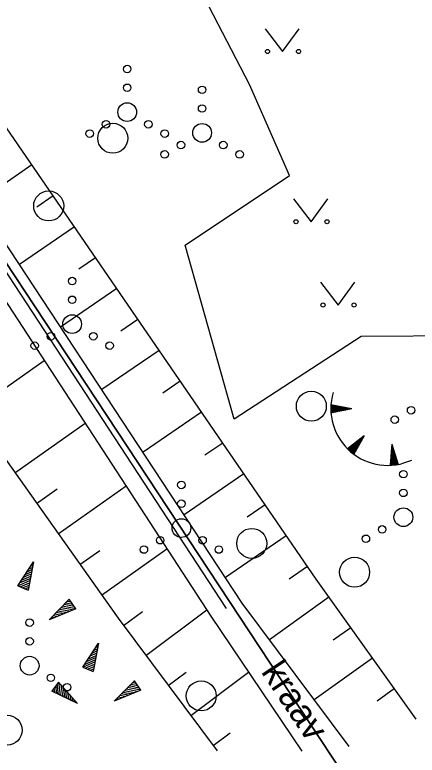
# Model space of a CAD drawing. Extents: x 554947 to 555436, y 6564938 to 6565792.
# Drawn here: x 555256.53 to 555267.27, y 6565099.76 to 6565119.52 of the extents above; entities that cross this region are included whole.
import ezdxf

# ---------------------------------------------------------------- set-up
doc = ezdxf.new("R2010")
doc.units = 0
for name, color, linetype in [('HALJASTUS', 7, 'Continuous'), ('PIIR', 7, 'Continuous'), ('RELJEEF', 7, 'Continuous'), ('VEEKOGU', 7, 'Continuous')]:
    doc.layers.add(name, color=color, linetype=linetype)

msp = doc.modelspace()

# ---------------------------------------------------------------- linework, layer by layer
at = {"layer": 'HALJASTUS'}
for p, q in [((555263.213, 6565119.152), (555263.676, 6565118.545)), ((555263.676, 6565118.545), (555264.122, 6565119.152)), ((555263.973, 6565114.606), (555264.437, 6565113.999)), ((555264.437, 6565113.999), (555264.882, 6565114.606)), ((555264.693, 6565112.382), (555265.157, 6565111.775)), ((555265.157, 6565111.775), (555265.602, 6565112.382))]:
    msp.add_line(p, q, dxfattribs=at)
msp.add_lwpolyline([(555277.06, 6565106.584), (555277.255, 6565111.788), (555268.557, 6565110.949), (555265.778, 6565110.936), (555262.384, 6565108.727), (555261.075, 6565113.375), (555263.858, 6565115.236), (555262.795, 6565117.659), (555261.001, 6565121.133), (555260.129, 6565122.751), (555257.76, 6565125.864), (555253.762, 6565133.295), (555248.914, 6565136.251)], dxfattribs=at)
for centre, radius in [((555263.275, 6565118.545), 0.055), ((555264.104, 6565118.545), 0.055), ((555259.533, 6565118.076), 0.1), ((555259.533, 6565117.576), 0.1), ((555261.531, 6565117.522), 0.1), ((555259.533, 6565116.926), 0.25), ((555261.531, 6565117.022), 0.1), ((555258.968, 6565116.601), 0.1), ((555260.098, 6565116.601), 0.1), ((555259.148, 6565116.228), 0.4), ((555261.531, 6565116.372), 0.25), ((555258.533, 6565116.351), 0.1), ((555260.533, 6565116.351), 0.1), ((555260.966, 6565116.047), 0.1), ((555262.096, 6565116.047), 0.1), ((555260.531, 6565115.797), 0.1), ((555262.531, 6565115.797), 0.1), ((555257.438, 6565114.421), 0.4), ((555264.036, 6565113.999), 0.055), ((555264.864, 6565113.999), 0.055), ((555258.064, 6565112.415), 0.1), ((555258.064, 6565111.915), 0.1), ((555264.756, 6565111.775), 0.055), ((555265.585, 6565111.775), 0.055), ((555258.064, 6565111.265), 0.25), ((555257.499, 6565110.94), 0.1), ((555258.629, 6565110.94), 0.1), ((555257.064, 6565110.69), 0.1), ((555259.064, 6565110.69), 0.1), ((555264.445, 6565109.073), 0.4), ((555267.106, 6565108.964), 0.1), ((555266.671, 6565108.714), 0.1), ((555266.9, 6565107.259), 0.1), ((555260.978, 6565106.97), 0.1), ((555266.9, 6565106.759), 0.1), ((555260.978, 6565106.47), 0.1), ((555266.9, 6565106.109), 0.25), ((555260.978, 6565105.82), 0.25), ((555262.855, 6565105.411), 0.4), ((555266.335, 6565105.784), 0.1), ((555265.9, 6565105.534), 0.1), ((555260.413, 6565105.495), 0.1), ((555261.543, 6565105.495), 0.1), ((555259.978, 6565105.245), 0.1), ((555261.978, 6565105.245), 0.1), ((555265.6, 6565104.64), 0.4), ((555256.93, 6565103.295), 0.1), ((555256.93, 6565102.795), 0.1), ((555256.93, 6565102.145), 0.25), ((555257.495, 6565101.82), 0.1), ((555257.93, 6565101.57), 0.1), ((555261.507, 6565101.339), 0.4), ((555256.331, 6565100.424), 0.4)]:
    msp.add_circle(centre, radius, dxfattribs=at)
at = {"layer": 'PIIR'}
for points in [[(555293.54, 6565286.23), (555256.63, 6565245.54), (555254.61, 6565228.5), (555255.75, 6565226.79), (555261.42, 6565218.27), (555289.11, 6565186.6), (555315.28, 6565149.09), (555315.73, 6565134.86), (555310.07, 6565124.47), (555303.59, 6565115.89), (555291.54, 6565100.48), (555288.85, 6565092.31), (555275.41, 6565088.83), (555273.15, 6565087.34), (555239.11, 6565139), (555231.12, 6565150.64), (555225.89, 6565157.13), (555173.21, 6565166.35), (555173.84, 6565168.77), (555191.64, 6565237.48), (555195.28, 6565271.63)], [(555272.013, 6565013.369), (555140.74, 6565041.04), (555172.58, 6565163.93), (555173.21, 6565166.35), (555225.89, 6565157.13), (555231.12, 6565150.64), (555239.11, 6565139), (555273.15, 6565087.34), (555275.41, 6565088.83), (555288.85, 6565092.31), (555289.83, 6565088.53), (555290.166, 6565088.221)]]:
    msp.add_lwpolyline(points, dxfattribs=at)
at = {"layer": 'RELJEEF'}
for p, q in [((555256.993, 6565115.514), (555255.559, 6565114.531)), ((555257.558, 6565114.689), (555257.123, 6565114.391)), ((555258.123, 6565113.864), (555256.658, 6565112.86)), ((555258.688, 6565113.039), (555258.244, 6565112.734)), ((555259.254, 6565112.214), (555257.757, 6565111.188)), ((555259.819, 6565111.389), (555259.365, 6565111.078)), ((555260.384, 6565110.564), (555258.856, 6565109.517)), ((555255.383, 6565108.927), (555257.316, 6565110.297)), ((555260.95, 6565109.739), (555260.486, 6565109.422)), ((555264.966, 6565109.046), (555265.033, 6565109.1)), ((555264.966, 6565109.014), (555265.065, 6565109.093)), ((555264.966, 6565108.982), (555265.097, 6565109.087)), ((555264.967, 6565109.079), (555265.001, 6565109.106)), ((555264.967, 6565108.951), (555265.129, 6565109.081)), ((555264.968, 6565108.92), (555265.162, 6565109.075)), ((555265.526, 6565109.004), (555264.969, 6565109.112)), ((555265.526, 6565109.004), (555264.97, 6565108.895)), ((555264.98, 6565108.897), (555265.194, 6565109.069)), ((555265.033, 6565108.908), (555265.226, 6565109.062)), ((555265.086, 6565108.918), (555265.258, 6565109.056)), ((555265.139, 6565108.929), (555265.291, 6565109.05)), ((555265.192, 6565108.939), (555265.323, 6565109.044)), ((555265.245, 6565108.949), (555265.355, 6565109.037)), ((555265.298, 6565108.96), (555265.387, 6565109.031)), ((555265.351, 6565108.97), (555265.42, 6565109.025)), ((555265.404, 6565108.981), (555265.452, 6565109.019)), ((555265.457, 6565108.991), (555265.484, 6565109.013)), ((555261.515, 6565108.915), (555259.955, 6565107.845)), ((555256.539, 6565107.295), (555258.409, 6565108.62)), ((555265.858, 6565108.284), (555265.413, 6565107.932)), ((555265.858, 6565108.284), (555265.578, 6565107.791)), ((555265.716, 6565108.035), (555265.721, 6565108.176)), ((555265.743, 6565108.082), (555265.747, 6565108.197)), ((555265.77, 6565108.129), (555265.773, 6565108.217)), ((555265.796, 6565108.176), (555265.799, 6565108.237)), ((555265.823, 6565108.223), (555265.824, 6565108.258)), ((555262.08, 6565108.09), (555261.608, 6565107.766)), ((555265.461, 6565107.887), (555265.464, 6565107.973)), ((555265.485, 6565107.866), (555265.49, 6565107.993)), ((555265.51, 6565107.845), (555265.516, 6565108.013)), ((555265.534, 6565107.825), (555265.541, 6565108.034)), ((555265.558, 6565107.806), (555265.567, 6565108.054)), ((555265.583, 6565107.801), (555265.593, 6565108.074)), ((555265.61, 6565107.848), (555265.619, 6565108.095)), ((555265.636, 6565107.895), (555265.644, 6565108.115)), ((555265.663, 6565107.941), (555265.67, 6565108.136)), ((555265.69, 6565107.988), (555265.696, 6565108.156)), ((555266.59, 6565108.06), (555266.548, 6565107.495)), ((555266.628, 6565107.942), (555266.584, 6565107.985)), ((555266.611, 6565107.994), (555266.587, 6565108.018)), ((555266.59, 6565108.06), (555266.763, 6565107.521)), ((555265.437, 6565107.91), (555265.438, 6565107.952)), ((555266.727, 6565107.633), (555266.57, 6565107.789)), ((555266.71, 6565107.685), (555266.572, 6565107.821)), ((555266.694, 6565107.736), (555266.575, 6565107.854)), ((555266.677, 6565107.788), (555266.577, 6565107.887)), ((555266.661, 6565107.839), (555266.579, 6565107.92)), ((555266.644, 6565107.891), (555266.582, 6565107.952)), ((555266.645, 6565107.503), (555266.555, 6565107.592)), ((555266.677, 6565107.507), (555266.557, 6565107.625)), ((555266.708, 6565107.511), (555266.56, 6565107.658)), ((555266.739, 6565107.516), (555266.562, 6565107.69)), ((555266.76, 6565107.531), (555266.565, 6565107.723)), ((555266.743, 6565107.582), (555266.567, 6565107.756)), ((555266.58, 6565107.497), (555266.55, 6565107.527)), ((555266.613, 6565107.499), (555266.552, 6565107.56)), ((555262.646, 6565107.265), (555261.054, 6565106.174)), ((555257.117, 6565106.479), (555257.668, 6565106.87)), ((555257.694, 6565105.663), (555259.502, 6565106.943)), ((555263.211, 6565106.44), (555262.729, 6565106.109)), ((555263.776, 6565105.615), (555262.153, 6565104.503)), ((555258.272, 6565104.847), (555258.805, 6565105.224)), ((555258.85, 6565104.031), (555260.594, 6565105.266)), ((555256.611, 6565104.278), (555257.031, 6565104.918)), ((555257.031, 6565104.918), (555256.891, 6565104.163)), ((555256.956, 6565104.803), (555257.016, 6565104.828)), ((555257.006, 6565104.878), (555257.026, 6565104.888)), ((555256.811, 6565104.578), (555256.981, 6565104.653)), ((555256.861, 6565104.653), (555256.991, 6565104.713)), ((555256.906, 6565104.728), (555257.006, 6565104.768)), ((555264.341, 6565104.79), (555263.852, 6565104.455)), ((555256.611, 6565104.278), (555256.936, 6565104.418)), ((555256.661, 6565104.353), (555256.946, 6565104.473)), ((555256.711, 6565104.428), (555256.961, 6565104.533)), ((555256.761, 6565104.503), (555256.886, 6565104.558)), ((555256.886, 6565104.558), (555256.971, 6565104.593)), ((555256.611, 6565104.278), (555256.891, 6565104.163)), ((555256.611, 6565104.278), (555256.611, 6565104.278)), ((555256.676, 6565104.253), (555256.926, 6565104.358)), ((555256.741, 6565104.223), (555256.916, 6565104.298)), ((555256.811, 6565104.198), (555256.906, 6565104.238)), ((555256.876, 6565104.173), (555256.891, 6565104.178)), ((555257.449, 6565103.372), (555257.989, 6565103.917)), ((555258.039, 6565103.842), (555257.939, 6565103.862)), ((555257.999, 6565103.902), (555257.979, 6565103.902)), ((555258.159, 6565103.667), (555257.989, 6565103.917)), ((555264.916, 6565103.972), (555263.331, 6565102.838)), ((555258.159, 6565103.667), (555257.449, 6565103.372)), ((555257.989, 6565103.597), (555257.724, 6565103.647)), ((555258.074, 6565103.632), (555257.769, 6565103.692)), ((555258.159, 6565103.667), (555257.809, 6565103.732)), ((555258.119, 6565103.722), (555257.854, 6565103.777)), ((555258.079, 6565103.782), (555257.894, 6565103.817)), ((555258.159, 6565103.667), (555258.159, 6565103.667)), ((555260.031, 6565102.417), (555261.659, 6565103.632)), ((555257.574, 6565103.422), (555257.514, 6565103.437)), ((555257.659, 6565103.457), (555257.554, 6565103.477)), ((555257.739, 6565103.492), (555257.599, 6565103.522)), ((555257.824, 6565103.527), (555257.639, 6565103.562)), ((555257.774, 6565103.587), (555257.684, 6565103.607)), ((555257.909, 6565103.562), (555257.774, 6565103.587)), ((555259.433, 6565103.218), (555259.937, 6565103.594)), ((555257.489, 6565103.387), (555257.474, 6565103.392)), ((555265.498, 6565103.158), (555265.027, 6565102.822)), ((555258.346, 6565102.105), (555258.766, 6565102.745)), ((555258.766, 6565102.745), (555258.626, 6565101.99)), ((555258.691, 6565102.63), (555258.751, 6565102.655)), ((555258.741, 6565102.705), (555258.761, 6565102.715)), ((555258.546, 6565102.405), (555258.716, 6565102.48)), ((555258.596, 6565102.48), (555258.726, 6565102.54)), ((555258.641, 6565102.555), (555258.741, 6565102.595)), ((555258.346, 6565102.105), (555258.671, 6565102.245)), ((555258.396, 6565102.18), (555258.681, 6565102.3)), ((555258.446, 6565102.255), (555258.696, 6565102.36)), ((555258.496, 6565102.33), (555258.621, 6565102.385)), ((555258.621, 6565102.385), (555258.706, 6565102.42)), ((555266.08, 6565102.345), (555264.524, 6565101.233)), ((555258.346, 6565102.105), (555258.626, 6565101.99)), ((555258.346, 6565102.105), (555258.346, 6565102.105)), ((555258.411, 6565102.08), (555258.661, 6565102.185)), ((555258.476, 6565102.05), (555258.651, 6565102.125)), ((555258.546, 6565102.025), (555258.641, 6565102.065)), ((555258.611, 6565102), (555258.626, 6565102.005)), ((555260.629, 6565101.616), (555261.105, 6565101.971)), ((555261.228, 6565100.814), (555262.773, 6565101.968)), ((555257.704, 6565101.704), (555257.519, 6565101.464)), ((555257.659, 6565101.649), (555257.694, 6565101.379)), ((555257.704, 6565101.704), (555258.209, 6565101.134)), ((555257.704, 6565101.704), (555257.749, 6565101.354)), ((555257.704, 6565101.704), (555257.704, 6565101.704)), ((555259.184, 6565101.199), (555259.724, 6565101.744)), ((555259.774, 6565101.669), (555259.674, 6565101.689)), ((555259.734, 6565101.729), (555259.714, 6565101.729)), ((555259.894, 6565101.494), (555259.724, 6565101.744)), ((555258.209, 6565101.134), (555257.519, 6565101.464)), ((555257.529, 6565101.479), (555257.534, 6565101.459)), ((555257.574, 6565101.534), (555257.589, 6565101.434)), ((555257.619, 6565101.594), (555257.644, 6565101.409)), ((555257.764, 6565101.639), (555257.804, 6565101.329)), ((555257.824, 6565101.569), (555257.859, 6565101.304)), ((555257.884, 6565101.504), (555257.899, 6565101.364)), ((555259.894, 6565101.494), (555259.184, 6565101.199)), ((555259.724, 6565101.424), (555259.459, 6565101.474)), ((555259.809, 6565101.459), (555259.504, 6565101.519)), ((555259.894, 6565101.494), (555259.544, 6565101.559)), ((555259.854, 6565101.549), (555259.589, 6565101.604)), ((555259.814, 6565101.609), (555259.629, 6565101.644)), ((555259.894, 6565101.494), (555259.894, 6565101.494)), ((555266.661, 6565101.532), (555266.199, 6565101.201)), ((555257.899, 6565101.364), (555257.914, 6565101.274)), ((555257.939, 6565101.434), (555257.969, 6565101.249)), ((555257.999, 6565101.369), (555258.019, 6565101.224)), ((555258.059, 6565101.299), (555258.074, 6565101.199)), ((555259.309, 6565101.249), (555259.249, 6565101.264)), ((555259.394, 6565101.284), (555259.289, 6565101.304)), ((555259.474, 6565101.319), (555259.334, 6565101.349)), ((555259.559, 6565101.354), (555259.374, 6565101.389)), ((555259.509, 6565101.414), (555259.419, 6565101.434)), ((555259.644, 6565101.389), (555259.509, 6565101.414)), ((555258.119, 6565101.234), (555258.129, 6565101.169)), ((555258.179, 6565101.164), (555258.184, 6565101.144)), ((555259.224, 6565101.214), (555259.209, 6565101.219)), ((555261.826, 6565100.013), (555262.277, 6565100.35))]:
    msp.add_line(p, q, dxfattribs=at)
msp.add_lwpolyline([(555267.243, 6565100.718), (555264.574, 6565104.451), (555253.061, 6565121.25), (555242.65, 6565138.338), (555234.145, 6565148.829), (555233.386, 6565148.636), (555231.367, 6565148.23), (555230.85, 6565146.543), (555236.09, 6565137.882), (555248.799, 6565118.225), (555259.289, 6565103.411), (555261.934, 6565099.868)], dxfattribs=at)
msp.add_arc((555266.479, 6565109.007), 1.514, 163.4234, 295.1745, dxfattribs=at)
at = {"layer": 'VEEKOGU'}
for points in [[(555265.45, 6565099.986), (555262.604, 6565103.817), (555251.937, 6565120.038), (555239.993, 6565138.74), (555233.721, 6565147.576), (555233.071, 6565146.869), (555239.071, 6565138.07), (555251.323, 6565119.495), (555261.764, 6565103.47), (555264.187, 6565099.861)], [(555239.299, 6565138.626), (555251.662, 6565119.733), (555262.176, 6565103.668)]]:
    msp.add_lwpolyline(points, dxfattribs=at)

# ---------------------------------------------------------------- texts
msp.add_text('kraav', height=0.7, rotation=303.5968, dxfattribs=at).set_placement((555263.091, 6565101.982))

doc.saveas('drawing.dxf')
